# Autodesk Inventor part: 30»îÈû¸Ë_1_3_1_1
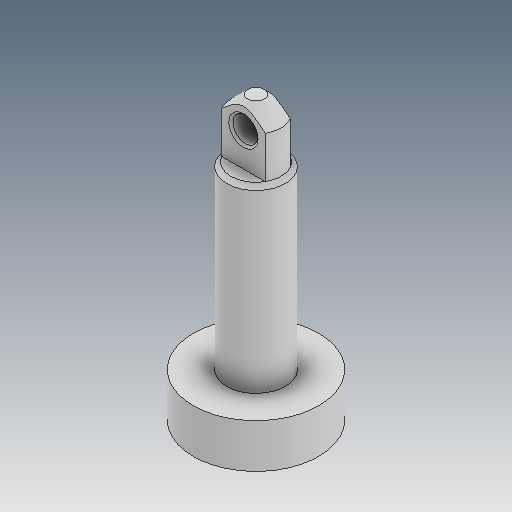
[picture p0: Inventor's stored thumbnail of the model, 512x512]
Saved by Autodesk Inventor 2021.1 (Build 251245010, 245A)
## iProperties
Created: 2019-04
Part Number: 30»îÈû¸Ë_1_3_1_1
Material: Ogólny
Document SubType Name: Modeling
Designer: user
Density: 1 g/cm^3
Appearance: Domyślna
Author: user
Revision Number: ÈÎºÎ
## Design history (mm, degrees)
feature "ÊäÈë1"
node "Bryła1"
